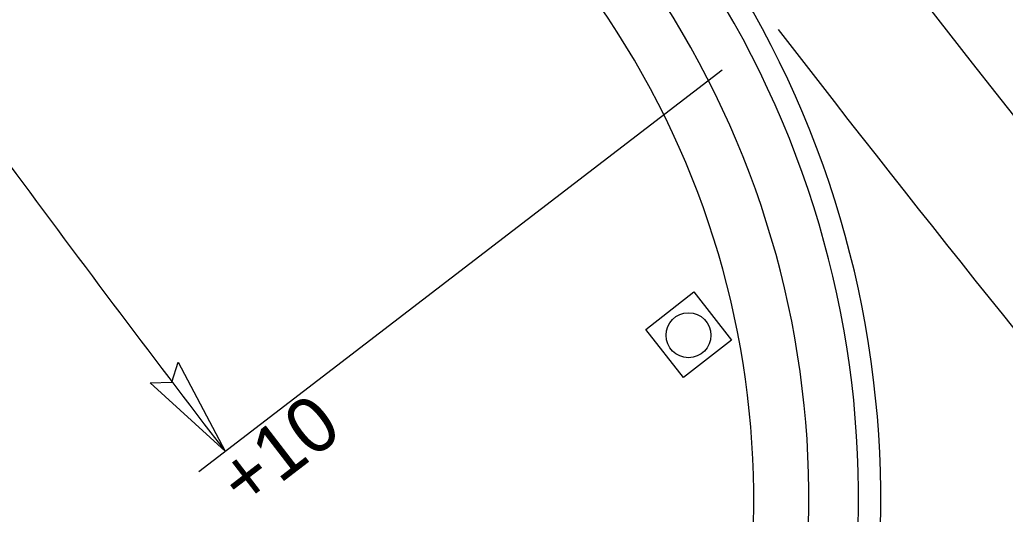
# Model space of a CAD drawing. Extents: x 1762196 to 1766326, y 709922 to 713142.
# Drawn here: x 1764013 to 1764102.2, y 711303.2 to 711348 of the extents above; entities that cross this region are included whole.
import ezdxf

# ---------------------------------------------------------------- set-up
doc = ezdxf.new("R2010")
doc.units = 0
for name, color, linetype in [('Default', 7, 'Continuous'), ('Pattern 1', 7, 'Continuous'), ('Pattern 2', 7, 'Continuous'), ('Prop Conc 2ft 6in Curb and Gutter', 7, 'Continuous'), ('Prop Dimension', 7, 'Continuous'), ('Prop EOT', 7, 'Continuous'), ('Prop Horizontal Alignment', 7, 'Continuous'), ('Prop Lane Lines', 7, 'Continuous'), ('Prop Terminator CELL', 7, 'Continuous')]:
    doc.layers.add(name, color=color, linetype=linetype)

msp = doc.modelspace()

# ---------------------------------------------------------------- linework, layer by layer
at = {"layer": 'Default'}
msp.add_lwpolyline([(1764077.441, 711318.973), (1764073.085, 711315.569), (1764069.682, 711319.924), (1764074.037, 711323.328)], close=True, dxfattribs=at)
msp.add_circle((1764073.542, 711319.403), 2.032, dxfattribs=at)
at = {"layer": 'Pattern 1'}
for radius in [83.5, 78.5]:
    msp.add_arc((1764000.949, 711304.582), radius, 328.29987, 36.99253, dxfattribs=at)
at = {"layer": 'Pattern 2'}
for radius in [83.5, 78.5]:
    msp.add_arc((1764000.949, 711304.582), radius, 328.29987, 36.99253, dxfattribs=at)
at = {"layer": 'Prop Conc 2ft 6in Curb and Gutter'}
msp.add_arc((1764000.949, 711304.582), 88, 328.29987, 36.99253, dxfattribs=at)
at = {"layer": 'Prop Dimension'}
msp.add_line((1764029.215, 711307.065), (1764076.59, 711343.459), dxfattribs=at)
msp.add_arc((1765296.463, 712280.557), 1595, 216.325025, 217.531253, dxfattribs=at)
at = {"layer": 'Prop EOT'}
msp.add_arc((1764000.949, 711304.582), 90, 328.29987, 36.99253, dxfattribs=at)
at = {"layer": 'Prop Horizontal Alignment'}
msp.add_arc((1765296.463, 712280.557), 1500, 216.325025, 240.843598, dxfattribs=at)
at = {"layer": 'Prop Lane Lines'}
for radius, start, end in [(1494, 216.325025, 222.114924), (1506, 216.325025, 222.114924), (1520, 216.325025, 224.729919), (1532, 217.538579, 222.471232)]:
    msp.add_arc((1765296.463, 712280.557), radius, start, end, dxfattribs=at)
at = {"layer": 'Prop Terminator CELL'}
msp.add_lwpolyline([(1764027.341, 711316.974), (1764031.594, 711308.893), (1764024.812, 711315.095), (1764026.782, 711315.158)], close=True, dxfattribs=at)

# ---------------------------------------------------------------- texts
at = {"layer": 'Prop Dimension'}
msp.add_text('+10', height=5, rotation=37.53125, dxfattribs=at).set_placement((1764033.423, 711303.504))

doc.saveas('drawing.dxf')
